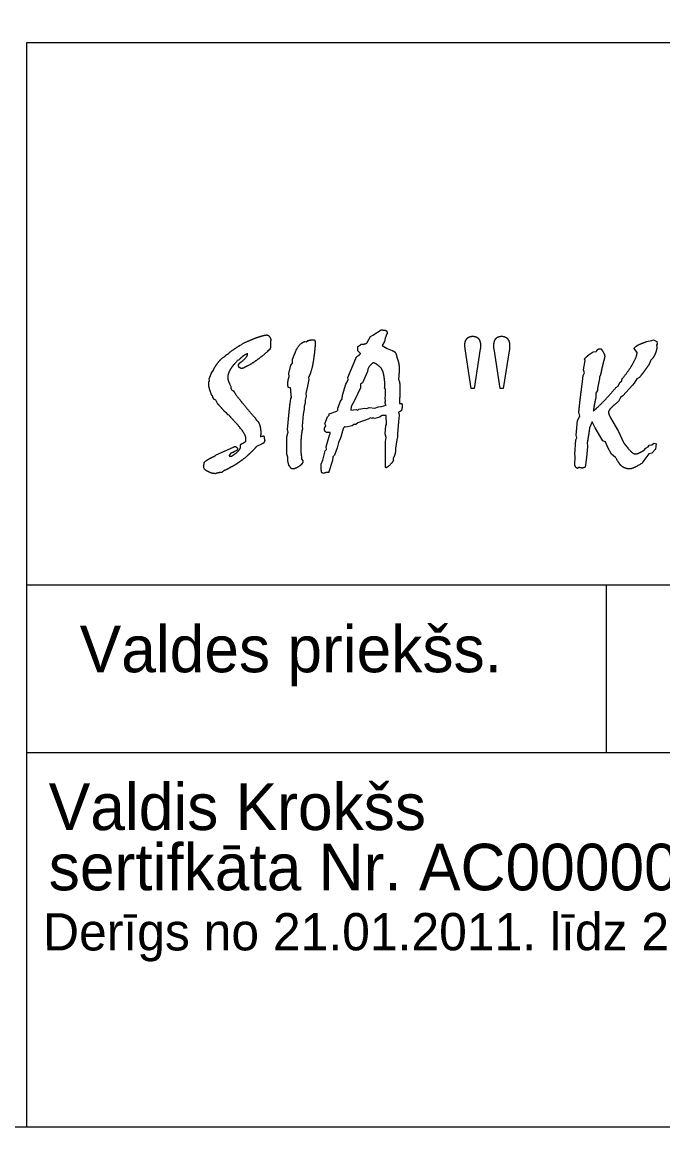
# Model space of a CAD drawing. Extents: x 728492 to 729038, y 272968 to 273171.
# Drawn here: x 728700.13 to 728713.89, y 272968.26 to 272991.99 of the extents above; entities that cross this region are included whole.
import ezdxf

# ---------------------------------------------------------------- set-up
doc = ezdxf.new("R2010")
doc.units = 0
doc.layers.add('RAMI_PLAN_####_TKST_#', color=7, linetype='Continuous')

msp = doc.modelspace()

# ---------------------------------------------------------------- linework, layer by layer
at = {"layer": 'RAMI_PLAN_####_TKST_#'}
for p, q in [((728700.236, 272991.547), (728765.305, 272991.547)), ((728700.236, 272968.264), (728700.236, 272991.547)), ((728700.236, 272979.905), (728738.292, 272979.905)), ((728712.679, 272976.305), (728712.679, 272979.905)), ((728700.236, 272976.305), (728738.292, 272976.305))]:
    msp.add_line(p, q, dxfattribs=at)
msp.add_lwpolyline([(728492.227, 273152.288), (728492.227, 272968.263), (728765.305, 272968.263), (728765.305, 273152.288)], close=True, dxfattribs=at)
for points in [[(728707.546, 272985.109), (728707.611, 272985.238), (728707.666, 272985.262), (728707.845, 272985.376)], [(728704.816, 272985.05), (728704.855, 272985.061), (728704.874, 272985.088)], [(728705.474, 272985.153), (728705.474, 272985.145), (728705.47, 272985.149), (728705.47, 272985.091), (728705.467, 272985.069), (728705.465, 272985.063)], [(728706.205, 272985.127), (728706.235, 272985.12), (728706.265, 272985.146)], [(728707.967, 272985.292), (728707.929, 272985.201), (728707.918, 272985.131), (728707.864, 272985.04), (728707.97, 272984.978), (728708.08, 272984.933)], [(728713.542, 272985.128), (728713.652, 272985.147), (728713.691, 272985.166), (728713.76, 272985.132), (728713.768, 272985.071), (728713.753, 272985.048), (728713.764, 272985.009)], [(728704.571, 272984.871), (728704.579, 272984.89)], [(728705.444, 272984.947), (728705.411, 272984.927), (728705.394, 272984.908)], [(728707.4, 272984.87), (728707.339, 272984.928), (728707.344, 272985.021)], [(728707.413, 272985.068), (728707.417, 272985.07)], [(728709.843, 272984.117), (728709.778, 272984.117), (728709.647, 272984.974)], [(728709.972, 272984.972), (728709.843, 272984.117)], [(728710.464, 272984.117), (728710.399, 272984.117), (728710.267, 272984.974)], [(728710.596, 272984.974), (728710.464, 272984.117)], [(728712.406, 272984.91), (728712.466, 272984.917)], [(728712.543, 272984.971), (728712.569, 272984.971)], [(728713.335, 272984.899), (728713.275, 272984.975)], [(728704.779, 272984.725), (728704.751, 272984.718), (728704.736, 272984.69)], [(728704.786, 272984.583), (728704.779, 272984.606)], [(728705.852, 272984.329), (728705.871, 272984.38), (728705.864, 272984.438), (728705.906, 272984.617), (728705.936, 272984.66), (728705.942, 272984.746)], [(728706.658, 272983.32), (728706.632, 272983.363), (728706.688, 272983.513), (728706.724, 272983.55), (728706.724, 272983.577), (728706.892, 272983.635), (728706.911, 272983.657), (728706.911, 272983.7), (728706.972, 272983.846), (728707.006, 272983.898), (728707.01, 272983.975), (728707.086, 272984.212), (728707.107, 272984.248), (728707.133, 272984.313), (728707.129, 272984.354), (728707.298, 272984.767)], [(728707.666, 272984.672), (728707.589, 272984.595), (728707.554, 272984.537), (728707.55, 272984.481), (728707.443, 272984.244), (728707.397, 272984.212), (728707.397, 272984.135), (728707.271, 272983.861), (728707.198, 272983.734), (728707.195, 272983.657)], [(728712.18, 272984.398), (728712.206, 272984.457), (728712.191, 272984.523), (728712.221, 272984.723), (728712.21, 272984.756)], [(728713.676, 272984.768), (728713.633, 272984.73), (728713.6, 272984.639)], [(728704.205, 272984.465), (728704.246, 272984.51), (728704.257, 272984.553)], [(728707.886, 272984.47), (728707.853, 272984.547)], [(728708.224, 272984.397), (728708.215, 272984.317), (728708.239, 272984.266)], [(728712.554, 272984.414), (728712.528, 272984.362), (728712.535, 272984.336), (728712.487, 272984.121), (728712.49, 272984.076), (728712.455, 272984.018), (728712.451, 272983.913)], [(728713.389, 272984.358), (728713.331, 272984.325), (728713.279, 272984.237), (728713.239, 272984.194), (728713.034, 272983.964), (728712.983, 272983.927), (728712.94, 272983.839)], [(728704.155, 272984.282), (728704.151, 272984.327)], [(728704.597, 272984.204), (728704.614, 272984.163), (728704.614, 272984.152), (728704.614, 272984.135)], [(728705.899, 272984.135), (728705.849, 272984.144)], [(728706.281, 272984.354), (728706.293, 272984.312), (728706.261, 272984.17), (728706.227, 272984.01), (728706.231, 272983.956), (728706.208, 272983.868), (728706.212, 272983.802), (728706.188, 272983.73), (728706.188, 272983.677), (728706.169, 272983.565), (728706.147, 272983.309), (728706.151, 272983.244)], [(728707.937, 272983.857), (728707.929, 272983.911), (728707.937, 272983.971), (728707.937, 272984.102), (728707.918, 272984.128)], [(728712.884, 272984.14), (728712.933, 272984.168), (728712.965, 272984.248), (728713.01, 272984.282), (728713.021, 272984.332)], [(728704.338, 272983.784), (728704.293, 272983.871), (728704.265, 272983.883), (728704.231, 272983.926), (728704.231, 272983.941)], [(728705.888, 272983.797), (728705.903, 272983.907), (728705.918, 272983.926)], [(728707.195, 272983.657), (728707.309, 272983.665), (728707.339, 272983.653), (728707.367, 272983.678), (728707.492, 272983.7), (728707.539, 272983.689), (728707.589, 272983.708), (728707.707, 272983.696), (728707.787, 272983.726), (728707.853, 272983.734), (728707.948, 272983.758)], [(728708.239, 272983.85), (728708.239, 272983.799), (728708.284, 272983.799)], [(728704.603, 272983.513), (728704.59, 272983.539), (728704.56, 272983.554), (728704.51, 272983.612), (728704.487, 272983.619)], [(728707.952, 272982.415), (728707.937, 272982.437), (728707.937, 272982.628), (728707.933, 272982.857), (728707.937, 272982.981), (728707.952, 272983.068), (728707.929, 272983.145), (728707.944, 272983.324), (728707.955, 272983.349), (728707.952, 272983.543), (728707.864, 272983.539), (728707.806, 272983.503), (728707.707, 272983.477), (728707.666, 272983.492), (728707.649, 272983.477), (728707.615, 272983.489), (728707.565, 272983.459), (728707.344, 272983.382), (728707.298, 272983.348), (728707.258, 272983.348), (728707.221, 272983.32), (728707.083, 272983.286), (728707.053, 272983.294)], [(728708.219, 272983.608), (728708.232, 272983.547), (728708.215, 272983.405), (728708.193, 272983.156), (728708.196, 272983.079), (728708.178, 272983.018), (728708.151, 272982.831), (728708.151, 272982.793)], [(728712.089, 272982.425), (728712.057, 272982.402), (728712.02, 272982.421), (728712.001, 272982.475), (728712.012, 272982.666), (728712.001, 272982.703), (728712.023, 272983.018), (728712.042, 272983.061), (728712.031, 272983.115), (728712.061, 272983.429), (728712.107, 272983.525), (728712.104, 272983.554), (728712.089, 272983.613)], [(728712.739, 272983.555), (728712.765, 272983.489), (728712.937, 272983.199), (728713.049, 272982.958)], [(728705.849, 272983.182), (728705.83, 272983.236)], [(728706.556, 272982.498), (728706.593, 272982.582), (728706.64, 272982.78), (728706.666, 272982.808), (728706.662, 272982.864), (728706.731, 272983.118), (728706.75, 272983.148), (728706.746, 272983.178), (728706.67, 272983.174)], [(728712.877, 272982.639), (728712.789, 272982.712), (728712.709, 272982.849), (728712.658, 272982.973), (728712.604, 272982.999), (728712.44, 272983.276), (728712.374, 272983.405), (728712.318, 272983.276)], [(728705.254, 272983.085), (728705.291, 272983.094)], [(728705.334, 272983.076), (728705.334, 272983.046)], [(728705.858, 272982.474), (728705.838, 272982.563), (728705.841, 272982.648), (728705.815, 272982.707), (728705.815, 272982.816), (728705.815, 272982.958), (728705.815, 272982.992)], [(728706.926, 272982.958), (728706.896, 272982.842), (728706.842, 272982.689), (728706.808, 272982.652), (728706.797, 272982.571)], [(728712.268, 272982.958), (728712.272, 272982.874), (728712.253, 272982.636), (728712.225, 272982.432)], [(728713.48, 272982.79), (728713.523, 272982.835), (728713.575, 272982.865), (728713.596, 272982.904), (728713.656, 272982.912), (728713.695, 272982.945), (728713.745, 272982.93), (728713.732, 272982.82), (728713.652, 272982.732), (728713.592, 272982.717), (728713.484, 272982.574), (728713.45, 272982.52), (728713.439, 272982.512)], [(728704.282, 272982.674), (728704.304, 272982.693), (728704.672, 272982.863)], [(728704.594, 272982.7), (728704.581, 272982.68)], [(728704.713, 272982.773), (728704.691, 272982.766), (728704.663, 272982.743)], [(728704.824, 272982.865), (728704.824, 272982.878), (728704.824, 272982.893)], [(728705.276, 272982.926), (728705.17, 272982.874), (728705.153, 272982.857)], [(728704.046, 272982.504), (728704.044, 272982.521)], [(728704.915, 272982.624), (728704.885, 272982.612), (728704.856, 272982.582)], [(728706.136, 272982.642), (728706.136, 272982.604), (728706.166, 272982.559)], [(728704.059, 272982.375), (728704.038, 272982.414)], [(728704.289, 272982.29), (728704.272, 272982.294), (728704.261, 272982.294)], [(728704.48, 272982.36), (728704.461, 272982.341), (728704.437, 272982.333), (728704.42, 272982.318)], [(728704.637, 272982.436), (728704.629, 272982.44)], [(728706.61, 272982.297), (728706.567, 272982.312)]]:
    msp.add_lwpolyline(points, dxfattribs=at)
for points in [[(728707.845, 272985.376), (728707.931, 272985.376), (728707.951, 272985.363)], [(728707.951, 272985.363), (728707.97, 272985.35), (728707.97, 272985.307)], [(728704.874, 272985.088), (728705.05, 272985.168), (728705.168, 272985.211)], [(728705.168, 272985.211), (728705.285, 272985.254), (728705.36, 272985.265)], [(728705.36, 272985.265), (728705.368, 272985.267), (728705.374, 272985.268)], [(728705.374, 272985.268), (728705.381, 272985.269), (728705.386, 272985.269)], [(728705.386, 272985.269), (728705.424, 272985.269), (728705.449, 272985.228)], [(728705.449, 272985.228), (728705.474, 272985.187), (728705.474, 272985.153)], [(728705.97, 272984.824), (728706.065, 272985.093), (728706.205, 272985.127)], [(728706.265, 272985.146), (728706.306, 272985.157), (728706.337, 272985.163)], [(728706.337, 272985.163), (728706.369, 272985.168), (728706.392, 272985.168)], [(728706.429, 272985.077), (728706.399, 272984.755), (728706.366, 272984.602)], [(728706.392, 272985.168), (728706.41, 272985.168), (728706.42, 272985.146)], [(728706.42, 272985.146), (728706.429, 272985.123), (728706.429, 272985.077)], [(728707.417, 272985.07), (728707.432, 272985.072), (728707.46, 272985.073)], [(728707.46, 272985.073), (728707.525, 272985.077), (728707.546, 272985.109)], [(728707.969, 272985.298), (728707.968, 272985.294), (728707.967, 272985.292)], [(728707.97, 272985.307), (728707.97, 272985.301), (728707.969, 272985.298)], [(728709.64, 272985.051), (728709.64, 272985.14), (728709.684, 272985.191)], [(728709.684, 272985.191), (728709.729, 272985.241), (728709.808, 272985.241)], [(728709.808, 272985.241), (728709.89, 272985.241), (728709.933, 272985.19)], [(728709.933, 272985.19), (728709.976, 272985.139), (728709.976, 272985.043)], [(728710.264, 272985.043), (728710.264, 272985.139), (728710.306, 272985.19)], [(728710.306, 272985.19), (728710.349, 272985.241), (728710.43, 272985.241)], [(728710.43, 272985.241), (728710.509, 272985.241), (728710.554, 272985.191)], [(728710.554, 272985.191), (728710.6, 272985.14), (728710.6, 272985.051)], [(728713.275, 272984.975), (728713.297, 272985.035), (728713.441, 272985.089)], [(728713.441, 272985.089), (728713.505, 272985.112), (728713.542, 272985.128)], [(728704.487, 272984.809), (728704.5, 272984.828), (728704.519, 272984.842)], [(728704.519, 272984.842), (728704.538, 272984.856), (728704.571, 272984.871)], [(728704.579, 272984.89), (728704.657, 272984.947), (728704.784, 272985.03)], [(728704.784, 272985.03), (728704.807, 272985.043), (728704.816, 272985.05)], [(728704.839, 272984.691), (728704.977, 272984.792), (728704.977, 272984.867)], [(728704.977, 272984.867), (728704.94, 272984.858), (728704.892, 272984.824)], [(728705.394, 272984.908), (728705.269, 272984.792), (728705.131, 272984.699)], [(728705.461, 272984.987), (728705.455, 272984.97), (728705.444, 272984.947)], [(728705.467, 272985.015), (728705.467, 272985.003), (728705.461, 272984.987)], [(728705.465, 272985.063), (728705.465, 272985.05), (728705.466, 272985.039)], [(728705.466, 272985.039), (728705.467, 272985.028), (728705.467, 272985.015)], [(728707.344, 272985.021), (728707.372, 272985.034), (728707.413, 272985.068)], [(728707.355, 272984.829), (728707.395, 272984.855), (728707.4, 272984.87)], [(728708.08, 272984.933), (728708.123, 272984.924), (728708.147, 272984.889)], [(728708.147, 272984.889), (728708.17, 272984.855), (728708.181, 272984.784)], [(728709.641, 272985.023), (728709.64, 272985.04), (728709.64, 272985.051)], [(728709.647, 272984.974), (728709.643, 272985.006), (728709.641, 272985.023)], [(728709.975, 272984.999), (728709.974, 272984.985), (728709.972, 272984.972)], [(728709.976, 272985.043), (728709.976, 272985.013), (728709.975, 272984.999)], [(728710.265, 272985.001), (728710.264, 272985.015), (728710.264, 272985.043)], [(728710.267, 272984.974), (728710.265, 272984.987), (728710.265, 272985.001)], [(728710.599, 272985.005), (728710.598, 272984.989), (728710.596, 272984.974)], [(728710.6, 272985.051), (728710.6, 272985.021), (728710.599, 272985.005)], [(728712.21, 272984.756), (728712.247, 272984.798), (728712.297, 272984.837)], [(728712.297, 272984.837), (728712.346, 272984.876), (728712.406, 272984.91)], [(728712.466, 272984.917), (728712.481, 272984.949), (728712.496, 272984.96)], [(728712.496, 272984.96), (728712.511, 272984.971), (728712.543, 272984.971)], [(728712.569, 272984.971), (728712.58, 272984.945), (728712.612, 272984.896)], [(728712.612, 272984.896), (728712.643, 272984.846), (728712.643, 272984.811)], [(728713.25, 272984.656), (728713.338, 272984.814), (728713.338, 272984.884)], [(728713.338, 272984.894), (728713.338, 272984.897), (728713.335, 272984.899)], [(728713.338, 272984.884), (728713.338, 272984.891), (728713.338, 272984.894)], [(728713.737, 272984.892), (728713.716, 272984.833), (728713.676, 272984.768)], [(728713.764, 272985.009), (728713.759, 272984.951), (728713.737, 272984.892)], [(728704.257, 272984.553), (728704.321, 272984.656), (728704.375, 272984.717)], [(728704.375, 272984.717), (728704.429, 272984.777), (728704.487, 272984.809)], [(728704.736, 272984.69), (728704.642, 272984.598), (728704.596, 272984.514)], [(728704.892, 272984.824), (728704.844, 272984.791), (728704.779, 272984.725)], [(728704.779, 272984.606), (728704.779, 272984.62), (728704.784, 272984.635)], [(728704.784, 272984.635), (728704.79, 272984.649), (728704.801, 272984.663)], [(728704.801, 272984.663), (728704.816, 272984.675), (728704.839, 272984.691)], [(728705.131, 272984.699), (728704.994, 272984.606), (728704.87, 272984.553)], [(728705.942, 272984.746), (728705.951, 272984.772), (728705.97, 272984.824)], [(728706.366, 272984.602), (728706.334, 272984.449), (728706.281, 272984.354)], [(728707.298, 272984.767), (728707.314, 272984.803), (728707.355, 272984.829)], [(728707.744, 272984.64), (728707.707, 272984.664), (728707.666, 272984.672)], [(728707.853, 272984.547), (728707.782, 272984.616), (728707.744, 272984.64)], [(728708.181, 272984.784), (728708.208, 272984.72), (728708.22, 272984.656)], [(728708.22, 272984.656), (728708.232, 272984.591), (728708.232, 272984.511)], [(728712.628, 272984.734), (728712.608, 272984.663), (728712.59, 272984.585)], [(728712.632, 272984.753), (728712.628, 272984.74), (728712.628, 272984.734)], [(728712.643, 272984.811), (728712.643, 272984.794), (728712.632, 272984.753)], [(728713.021, 272984.332), (728713.161, 272984.499), (728713.25, 272984.656)], [(728713.6, 272984.639), (728713.529, 272984.54), (728713.482, 272984.477)], [(728704.151, 272984.327), (728704.156, 272984.342), (728704.176, 272984.39)], [(728704.176, 272984.39), (728704.196, 272984.437), (728704.205, 272984.465)], [(728704.596, 272984.514), (728704.549, 272984.43), (728704.549, 272984.35)], [(728704.818, 272984.558), (728704.801, 272984.566), (728704.786, 272984.583)], [(728704.848, 272984.55), (728704.835, 272984.55), (728704.818, 272984.558)], [(728704.86, 272984.55), (728704.855, 272984.55), (728704.848, 272984.55)], [(728704.87, 272984.553), (728704.865, 272984.551), (728704.86, 272984.55)], [(728707.912, 272984.335), (728707.903, 272984.408), (728707.886, 272984.47)], [(728708.226, 272984.442), (728708.224, 272984.412), (728708.224, 272984.397)], [(728708.232, 272984.511), (728708.232, 272984.496), (728708.226, 272984.442)], [(728712.134, 272984.018), (728712.169, 272984.28), (728712.18, 272984.398)], [(728712.59, 272984.585), (728712.572, 272984.508), (728712.554, 272984.414)], [(728713.482, 272984.477), (728713.435, 272984.414), (728713.389, 272984.358)], [(728704.14, 272984.232), (728704.14, 272984.243), (728704.143, 272984.256)], [(728704.158, 272984.111), (728704.14, 272984.18), (728704.14, 272984.232)], [(728704.143, 272984.256), (728704.147, 272984.269), (728704.155, 272984.282)], [(728704.549, 272984.35), (728704.549, 272984.318), (728704.561, 272984.282)], [(728704.561, 272984.282), (728704.573, 272984.247), (728704.597, 272984.204)], [(728704.614, 272984.135), (728704.614, 272984.116), (728704.63, 272984.097)], [(728705.838, 272984.24), (728705.838, 272984.251), (728705.847, 272984.298)], [(728705.84, 272984.199), (728705.838, 272984.223), (728705.838, 272984.24)], [(728705.849, 272984.144), (728705.843, 272984.176), (728705.84, 272984.199)], [(728705.847, 272984.298), (728705.851, 272984.318), (728705.852, 272984.329)], [(728705.906, 272984.038), (728705.901, 272984.088), (728705.899, 272984.135)], [(728707.922, 272984.208), (728707.922, 272984.263), (728707.912, 272984.335)], [(728707.918, 272984.128), (728707.92, 272984.15), (728707.921, 272984.168)], [(728707.921, 272984.168), (728707.922, 272984.186), (728707.922, 272984.208)], [(728708.239, 272984.266), (728708.239, 272984.249), (728708.241, 272984.22)], [(728708.241, 272984.22), (728708.247, 272984.119), (728708.247, 272984.087)], [(728712.631, 272983.856), (728712.752, 272983.983), (728712.884, 272984.14)], [(728704.212, 272983.963), (728704.177, 272984.043), (728704.158, 272984.111)], [(728704.226, 272983.955), (728704.222, 272983.961), (728704.212, 272983.963)], [(728704.231, 272983.941), (728704.231, 272983.95), (728704.226, 272983.955)], [(728704.63, 272984.097), (728704.646, 272984.079), (728704.67, 272984.071)], [(728704.67, 272984.071), (728704.721, 272983.987), (728704.841, 272983.837)], [(728705.918, 272983.926), (728705.91, 272983.987), (728705.906, 272984.038)], [(728708.243, 272983.978), (728708.239, 272983.898), (728708.239, 272983.85)], [(728708.247, 272984.087), (728708.247, 272984.057), (728708.243, 272983.978)], [(728712.089, 272983.613), (728712.1, 272983.756), (728712.134, 272984.018)], [(728712.451, 272983.913), (728712.438, 272983.869), (728712.426, 272983.806)], [(728704.414, 272983.703), (728704.377, 272983.744), (728704.338, 272983.784)], [(728704.487, 272983.619), (728704.452, 272983.662), (728704.414, 272983.703)], [(728704.841, 272983.837), (728704.96, 272983.687), (728705.142, 272983.481)], [(728705.865, 272983.583), (728705.877, 272983.698), (728705.888, 272983.797)], [(728707.929, 272983.81), (728707.929, 272983.822), (728707.935, 272983.846)], [(728707.933, 272983.794), (728707.929, 272983.807), (728707.929, 272983.81)], [(728707.948, 272983.758), (728707.937, 272983.782), (728707.933, 272983.794)], [(728707.935, 272983.846), (728707.935, 272983.851), (728707.937, 272983.857)], [(728708.28, 272983.653), (728708.269, 272983.64), (728708.256, 272983.63)], [(728708.286, 272983.678), (728708.282, 272983.663), (728708.28, 272983.653)], [(728708.284, 272983.799), (728708.292, 272983.773), (728708.294, 272983.759)], [(728708.295, 272983.734), (728708.295, 272983.719), (728708.286, 272983.678)], [(728708.294, 272983.759), (728708.295, 272983.745), (728708.295, 272983.734)], [(728712.399, 272983.635), (728712.511, 272983.73), (728712.631, 272983.856)], [(728712.426, 272983.806), (728712.414, 272983.743), (728712.399, 272983.635)], [(728712.774, 272983.696), (728712.724, 272983.642), (728712.724, 272983.609)], [(728712.94, 272983.839), (728712.825, 272983.749), (728712.774, 272983.696)], [(728704.678, 272983.431), (728704.629, 272983.483), (728704.603, 272983.513)], [(728704.94, 272983.042), (728704.94, 272983.154), (728704.678, 272983.431)], [(728705.142, 272983.481), (728705.149, 272983.46), (728705.162, 272983.445)], [(728705.162, 272983.445), (728705.175, 272983.429), (728705.199, 272983.412)], [(728705.199, 272983.412), (728705.229, 272983.358), (728705.243, 272983.304)], [(728705.83, 272983.236), (728705.854, 272983.468), (728705.865, 272983.583)], [(728708.256, 272983.63), (728708.243, 272983.62), (728708.219, 272983.608)], [(728712.724, 272983.609), (728712.724, 272983.596), (728712.733, 272983.571)], [(728712.733, 272983.571), (728712.737, 272983.56), (728712.739, 272983.555)], [(728705.243, 272983.304), (728705.257, 272983.251), (728705.257, 272983.186)], [(728705.257, 272983.186), (728705.257, 272983.154), (728705.256, 272983.131)], [(728705.824, 272983.1), (728705.832, 272983.145), (728705.849, 272983.182)], [(728706.151, 272983.244), (728706.132, 272983.162), (728706.124, 272983.061)], [(728706.623, 272983.247), (728706.625, 272983.266), (728706.631, 272983.281)], [(728706.634, 272983.211), (728706.623, 272983.228), (728706.623, 272983.247)], [(728706.631, 272983.281), (728706.638, 272983.296), (728706.658, 272983.32)], [(728706.67, 272983.174), (728706.645, 272983.193), (728706.634, 272983.211)], [(728707.053, 272983.294), (728707.032, 272983.282), (728707.003, 272983.167)], [(728712.318, 272983.276), (728712.303, 272983.164), (728712.291, 272983.089)], [(728704.835, 272982.926), (728704.863, 272982.939), (728704.889, 272982.954)], [(728704.889, 272982.954), (728704.915, 272982.969), (728704.936, 272982.984)], [(728704.936, 272982.984), (728704.938, 272982.997), (728704.939, 272983.009)], [(728704.939, 272983.009), (728704.94, 272983.021), (728704.94, 272983.042)], [(728705.256, 272983.131), (728705.256, 272983.107), (728705.254, 272983.085)], [(728705.324, 272982.955), (728705.31, 272982.939), (728705.276, 272982.926)], [(728705.291, 272983.094), (728705.295, 272983.096), (728705.299, 272983.099)], [(728705.299, 272983.099), (728705.304, 272983.102), (728705.306, 272983.102)], [(728705.306, 272983.102), (728705.315, 272983.102), (728705.323, 272983.094)], [(728705.323, 272983.094), (728705.33, 272983.087), (728705.334, 272983.076)], [(728705.342, 272982.999), (728705.338, 272982.971), (728705.324, 272982.955)], [(728705.334, 272983.046), (728705.334, 272983.042), (728705.337, 272983.027)], [(728705.337, 272983.027), (728705.34, 272983.012), (728705.342, 272982.999)], [(728705.815, 272982.992), (728705.815, 272983.055), (728705.824, 272983.1)], [(728706.124, 272983.061), (728706.117, 272982.96), (728706.117, 272982.805)], [(728707.003, 272983.167), (728706.974, 272983.051), (728706.926, 272982.958)], [(728712.291, 272983.089), (728712.279, 272983.014), (728712.268, 272982.958)], [(728713.049, 272982.958), (728713.06, 272982.941), (728713.082, 272982.912)], [(728704.618, 272982.73), (728704.603, 272982.721), (728704.594, 272982.7)], [(728704.607, 272982.663), (728704.646, 272982.663), (728704.735, 272982.739)], [(728704.663, 272982.743), (728704.633, 272982.739), (728704.618, 272982.73)], [(728704.672, 272982.863), (728704.682, 272982.868), (728704.69, 272982.871)], [(728704.69, 272982.871), (728704.698, 272982.874), (728704.706, 272982.874)], [(728704.706, 272982.874), (728704.723, 272982.874), (728704.741, 272982.856)], [(728704.748, 272982.798), (728704.736, 272982.784), (728704.713, 272982.773)], [(728704.735, 272982.739), (728704.824, 272982.816), (728704.824, 272982.865)], [(728704.741, 272982.856), (728704.76, 272982.838), (728704.76, 272982.827)], [(728704.76, 272982.827), (728704.76, 272982.812), (728704.748, 272982.798)], [(728704.824, 272982.893), (728704.824, 272982.9), (728704.827, 272982.908)], [(728704.827, 272982.908), (728704.829, 272982.917), (728704.835, 272982.926)], [(728705.051, 272982.751), (728704.994, 272982.695), (728704.915, 272982.624)], [(728705.153, 272982.857), (728705.108, 272982.807), (728705.051, 272982.751)], [(728706.117, 272982.805), (728706.117, 272982.777), (728706.121, 272982.739)], [(728706.121, 272982.739), (728706.124, 272982.702), (728706.136, 272982.642)], [(728708.138, 272982.709), (728708.125, 272982.665), (728708.097, 272982.616)], [(728708.151, 272982.793), (728708.151, 272982.752), (728708.138, 272982.709)], [(728713.082, 272982.912), (728713.232, 272982.713), (728713.301, 272982.713)], [(728713.301, 272982.713), (728713.329, 272982.713), (728713.374, 272982.732)], [(728713.374, 272982.732), (728713.419, 272982.751), (728713.48, 272982.79)], [(728704.035, 272982.448), (728704.035, 272982.465), (728704.037, 272982.479)], [(728704.037, 272982.479), (728704.04, 272982.493), (728704.046, 272982.504)], [(728704.044, 272982.521), (728704.046, 272982.543), (728704.114, 272982.588)], [(728704.114, 272982.588), (728704.182, 272982.633), (728704.282, 272982.674)], [(728704.581, 272982.68), (728704.582, 272982.676), (728704.588, 272982.67)], [(728704.588, 272982.67), (728704.599, 272982.663), (728704.607, 272982.663)], [(728704.741, 272982.501), (728704.687, 272982.466), (728704.637, 272982.436)], [(728704.856, 272982.582), (728704.794, 272982.537), (728704.741, 272982.501)], [(728705.898, 272982.424), (728705.877, 272982.457), (728705.858, 272982.474)], [(728706.136, 272982.494), (728706.113, 272982.466), (728706.063, 272982.436)], [(728706.166, 272982.559), (728706.158, 272982.522), (728706.136, 272982.494)], [(728706.552, 272982.448), (728706.552, 272982.469), (728706.553, 272982.48)], [(728706.553, 272982.48), (728706.554, 272982.491), (728706.556, 272982.498)], [(728706.797, 272982.571), (728706.769, 272982.484), (728706.749, 272982.423)], [(728708.105, 272982.583), (728708.105, 272982.53), (728707.974, 272982.431)], [(728708.097, 272982.616), (728708.101, 272982.607), (728708.103, 272982.597)], [(728708.103, 272982.597), (728708.105, 272982.586), (728708.105, 272982.583)], [(728712.998, 272982.462), (728712.948, 272982.509), (728712.877, 272982.639)], [(728713.12, 272982.398), (728713.049, 272982.415), (728712.998, 272982.462)], [(728713.439, 272982.512), (728713.249, 272982.391), (728713.17, 272982.391)], [(728704.036, 272982.432), (728704.035, 272982.444), (728704.035, 272982.448)], [(728704.038, 272982.414), (728704.038, 272982.42), (728704.036, 272982.432)], [(728704.17, 272982.314), (728704.121, 272982.333), (728704.059, 272982.375)], [(728704.261, 272982.294), (728704.22, 272982.294), (728704.17, 272982.314)], [(728704.35, 272982.308), (728704.317, 272982.301), (728704.289, 272982.29)], [(728704.42, 272982.318), (728704.383, 272982.315), (728704.35, 272982.308)], [(728704.563, 272982.397), (728704.528, 272982.378), (728704.48, 272982.36)], [(728704.629, 272982.44), (728704.597, 272982.416), (728704.563, 272982.397)], [(728705.94, 272982.391), (728705.919, 272982.391), (728705.898, 272982.424)], [(728705.995, 272982.401), (728705.966, 272982.391), (728705.94, 272982.391)], [(728706.063, 272982.436), (728706.024, 272982.411), (728705.995, 272982.401)], [(728706.555, 272982.395), (728706.552, 272982.424), (728706.552, 272982.448)], [(728706.567, 272982.312), (728706.558, 272982.366), (728706.555, 272982.395)], [(728706.643, 272982.309), (728706.627, 272982.304), (728706.61, 272982.297)], [(728706.677, 272982.316), (728706.66, 272982.314), (728706.643, 272982.309)], [(728706.7, 272982.314), (728706.692, 272982.316), (728706.677, 272982.316)], [(728706.713, 272982.312), (728706.707, 272982.312), (728706.7, 272982.314)], [(728706.749, 272982.423), (728706.729, 272982.362), (728706.713, 272982.312)], [(728707.974, 272982.431), (728707.959, 272982.42), (728707.952, 272982.415)], [(728712.111, 272982.419), (728712.096, 272982.423), (728712.089, 272982.425)], [(728712.158, 272982.41), (728712.145, 272982.41), (728712.111, 272982.419)], [(728712.186, 272982.415), (728712.169, 272982.41), (728712.158, 272982.41)], [(728712.225, 272982.432), (728712.203, 272982.421), (728712.186, 272982.415)], [(728713.149, 272982.393), (728713.137, 272982.395), (728713.12, 272982.398)], [(728713.17, 272982.391), (728713.161, 272982.391), (728713.149, 272982.393)]]:
    msp.add_open_spline(points, degree=2, dxfattribs=at)

# ---------------------------------------------------------------- texts
for s, height, rotation, p in [('Valdes priekšs.', 1, 359.9999, (728701.37, 272978.026)), ('Valdis Krokšs', 1, 359.9999, (728700.705, 272974.638)), ('sertifkāta Nr. AC000000071', 1, 359.9999, (728700.705, 272973.344)), ('Derīgs no 21.01.2011. līdz 20.01.2016.', 0.8, 0.0269, (728700.584, 272972.052))]:
    msp.add_text(s, height=height, rotation=rotation, dxfattribs=at).set_placement(p)

doc.saveas('drawing.dxf')
